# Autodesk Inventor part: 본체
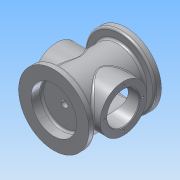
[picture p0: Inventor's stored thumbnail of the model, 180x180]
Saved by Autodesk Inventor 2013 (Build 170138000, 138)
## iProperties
Created: 2018-02
Part Number: 본체
Material: 알루미늄 6061
Document SubType Name: Modeling
Designer: Administrator
Density: 2.71 g/cm^3
Mass: 773.669 g
Surface Area: 833.4 cm^2
Volume: 285.487 cm^3
Author: Administrator
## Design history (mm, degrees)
sketch "스케치1"
  geometry: C1 r 38 at (0, 0); 1 further point
  constraints: 1 centre point, 1 coincident
  dimensions: "d0" = 76 diameter of C1
extrude "돌출1" new body sketch "스케치1" stored distance "d1" = 88; taper "d2" = 0 deg
sketch "스케치2"
  geometry: C1 r 52.5 at (0, 0); 1 further point
  constraints: 1 centre point, 1 coincident
  dimensions: "d3" = 105 diameter of C1
extrude "돌출2" join sketch "스케치2" distance "d4" = 10; taper "d5" = 0 deg
sketch "스케치3"
  geometry: C1 r 37 at (0, 0); 1 further point
  constraints: 1 centre point, 1 coincident
  dimensions: "d6" = 74 diameter of C1
extrude "돌출3" cut sketch "스케치3" distance "d7" = 7; taper "d8" = 0 deg
sketch "스케치4"
  geometry: C1 r 33 at (0, 0); 1 further point
  constraints: 1 centre point, 1 coincident
  dimensions: "d9" = 66 diameter of C1
extrude "돌출4" cut sketch "스케치4" distance "d10" = 79; taper "d11" = 0 deg
sketch "스케치5"
  geometry: C1 r 34 at (0, 0); 1 further point
  constraints: 1 centre point, 1 coincident
  dimensions: "d12" = 68 diameter of C1
extrude "돌출5" cut sketch "스케치5" distance "d13" = 16; taper "d14" = 0 deg
sketch "스케치6"
  geometry: C1 r 5 at (0, 0); 1 further point
  constraints: 1 centre point, 1 coincident
  dimensions: "d15" = 10 diameter of C1
extrude "돌출6" cut sketch "스케치6" stored distance "d16" = 16; taper "d17" = 0 deg
node "작업 평면1"
sketch "스케치7"
  geometry: C1 r 35 at (0, 0); 1 further point
  constraints: 1 centre point, 1 coincident
  dimensions: "d19" = 70 diameter of C1
extrude "돌출7" join sketch "스케치7" stored distance "d20" = 16; taper "d21" = 0 deg
sketch "스케치8"
  geometry: C1 r 24 at (0, 0); 1 further point
  constraints: 1 centre point, 1 coincident
  dimensions: "d22" = 48 diameter of C1
extrude "돌출8" cut sketch "스케치8" stored distance "d23" = 48 (= d22); taper "d24" = 0 deg
sketch "스케치9"
  geometry: 2 further points
  constraints: 1 vertical alignment
  dimensions: "d25" = 29 distance of point (0, 0) point (0, 29)
hole "구멍1" sketch "스케치9" at (0, 29) diameter "d26" = 3.242; stored, may be unused: countersink angle "d30" = 90 deg, drill point angle "d32" = 118 deg; dims "d27" = 4, "d28" = 4, "d29" = 2, "d31" = 6
chamfer "모따기1" distance "d36" = 1; stored, may be unused: second distance "d37" = 2, angle "d38" = 45 deg
fillet "모깎기1" dims "d39" = 3
node "작업 평면2"
sketch "스케치10"
  geometry: L1 (-7, 13)-(-7, -13); L2 (7, 13)-(7, -13); A1 r 7 centre (0, 13) between (7, 13) and (-7, 13); A2 r 7 centre (0, -13) between (-7, -13) and (7, -13); 2 further points
  constraints: 4 end point, 4 point on circle, 4 tangent, 2 centre point, 2 vertical alignment, 1 horizontal alignment, 1 midpoint
  dimensions: "d41" = 14 diameter of A1; "d42" = 14 diameter of A2; "d43" = 40 dimension on A2 A1
extrude "돌출9" join sketch "스케치10" stored distance "d44" = 16; taper "d45" = 15 deg
sketch "스케치11"
  geometry: A1 r 7 centre (0, 13) between (7, 13) and (-7, 13) reference; A2 r 7 centre (0, -13) between (-7, -13) and (7, -13) reference; 3 further points
  constraints: 2 coincident
hole "구멍2" sketch "스케치11" at (0, 13), (0, -13) diameter "d46" = 4.134; stored, may be unused: countersink angle "d50" = 90 deg, drill point angle "d52" = 118 deg; dims "d47" = 6, "d48" = 4, "d49" = 2, "d51" = 8
fillet "모깎기2" dims "d53" = 3
sketch "스케치12"
  geometry: C1 r 43 at (0, 0); 1 further point
  constraints: 1 centre point, 1 coincident, 1 other
  dimensions: "d54" = 86 diameter of C1
feature "엠보싱1" sketch "스케치12" dims "d55" = 0.5, "d56" = 0
fillet "모깎기3" dims "d57" = 3
fillet "모깎기4" dims "d58" = 3
sketch "스케치13"
  geometry: 2 further points
  constraints: 1 vertical alignment
  dimensions: "d59" = 45 distance of point (0, 0) point (0, 45)
hole "구멍3" sketch "스케치13" at (0, 45) diameter "d60" = 3.242; stored, may be unused: countersink angle "d64" = 90 deg, drill point angle "d66" = 118 deg; dims "d61" = 4, "d62" = 4, "d63" = 2, "d65" = 6
node "솔리드1"
mirror "대칭1"
pattern_circular "원형 패턴1" dims angle "d34" = 360 deg
mirror "대칭2"
pattern_circular "원형 패턴2" dims angle "d68" = 360 deg
other parameters: "d40" = -55
